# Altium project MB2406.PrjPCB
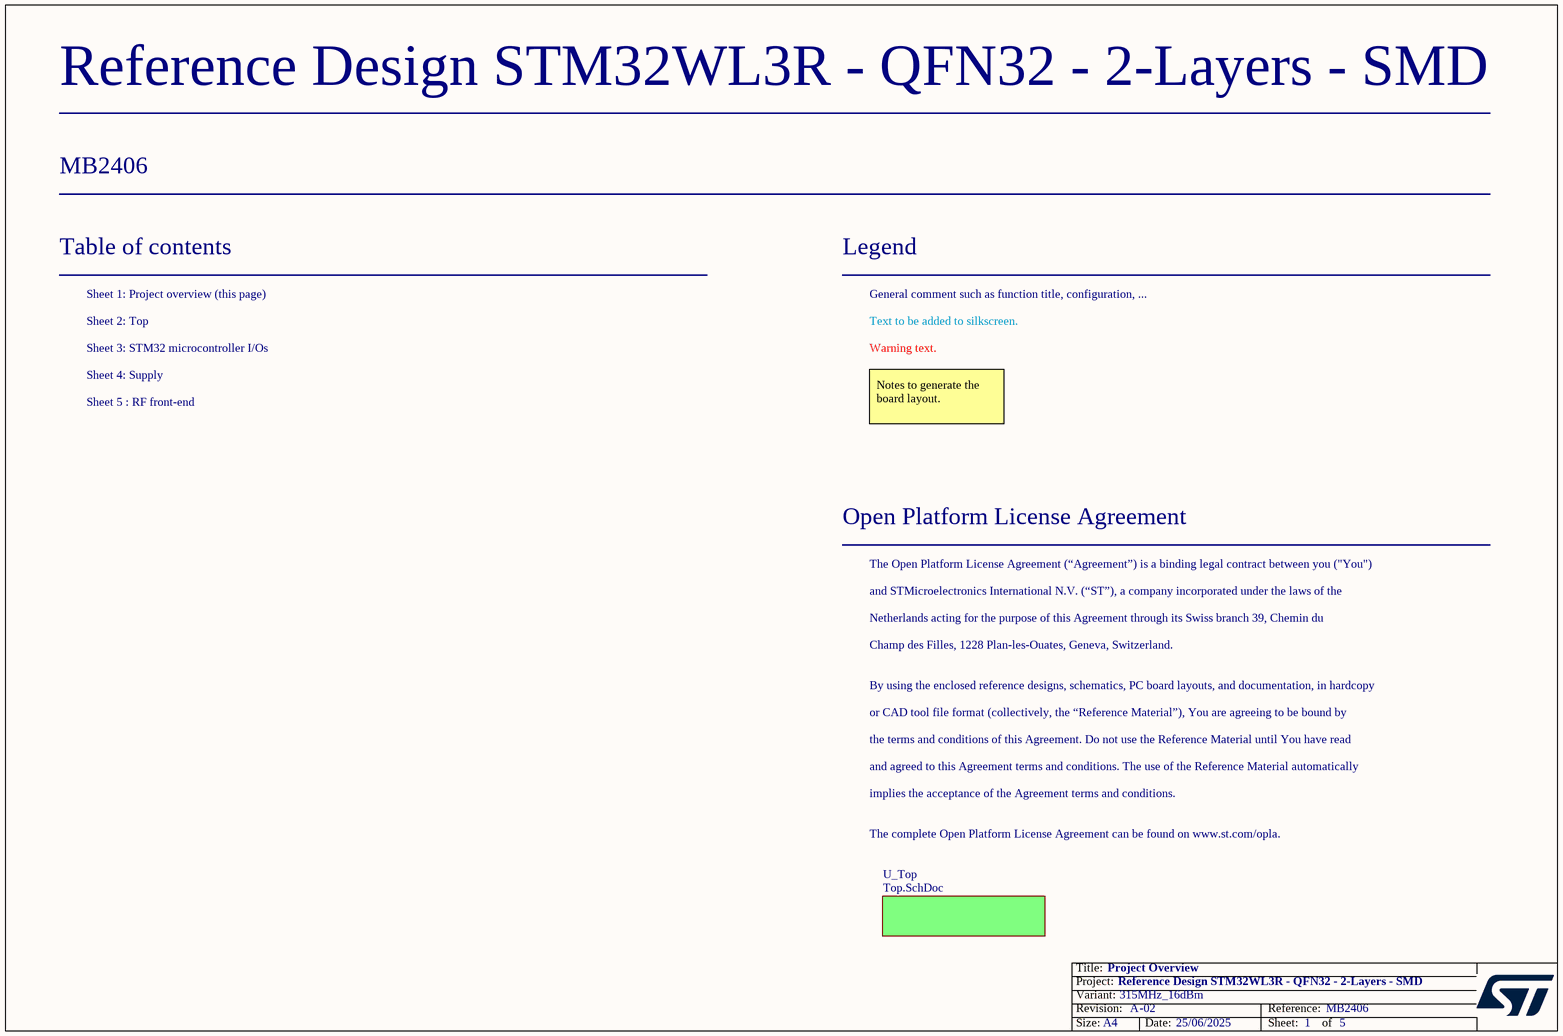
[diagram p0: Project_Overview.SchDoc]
Board_Assembly_Revision: 02; Board_Document_Date: 25/06/2025; Board_Name: Reference Design STM32WL3R - QFN32 - 2-Layers - SMD; Board_PCB_Revision: A; Board_Reference: MB2406; VariantName: 315MHz_16dBm
5 sheets, 71 parts. Net scope: flat (ports and power ports of the same name join across sheets).
Board file: MB2406.PcbDoc
Sheets:
  Project_Overview.SchDoc
    U_Top = Top.SchDoc
      Designator = MCU_IOs.SchDoc
      Designator = RF.SchDoc
      Designator = Supply.SchDoc

## Sheet Project_Overview.SchDoc: Project Overview
size A4; Date: Not used; ApprovedBy: Not used; CheckedBy: Not used; Author: Not used; CompanyName: STMicroelectronics; DrawnBy: Not used; Engineer: Not used; Organization: Not used; Address1: Not used; Address2: Not used; Address3: Not used; Address4: Not used; DocumentNumber: Not used; Revision: Not used; SheetNumber: 1; SheetTotal: 5

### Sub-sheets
U_Top = Top.SchDoc: no entries

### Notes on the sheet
- Table of contents
- Sheet 1: Project overview (this page)
- Legend
- General comment such as function title, configuration, ...
- Sheet 2: Top
- Sheet 3: STM32 microcontroller I/Os
- Sheet 4: Supply
- Text to be added to silkscreen.
- Warning text.
- Sheet 5 : RF front-end
- Notes to generate the board layout.
- Open Platform License Agreement
- The Open Platform License Agreement (“Agreement”) is a binding legal contract between you ("You")
- and STMicroelectronics International N.V. (“ST”), a company incorporated under the laws of the
- Netherlands acting for the purpose of this Agreement through its Swiss branch 39, Chemin du
- Champ des Filles, 1228 Plan-les-Ouates, Geneva, Switzerland.
- By using the enclosed reference designs, schematics, PC board layouts, and documentation, in hardcopy
- or CAD tool file format (collectively, the “Reference Material”), You are agreeing to be bound by
- the terms and conditions of this Agreement. Do not use the Reference Material until You have read
- and agreed to this Agreement terms and conditions. The use of the Reference Material automatically
- implies the acceptance of the Agreement terms and conditions.
- The complete Open Platform License Agreement can be found on www.st.com/opla.

## Sheet Top.SchDoc: Top Schematic
size A4; Date: Not used; ApprovedBy: Not used; CheckedBy: Not used; Author: Not used; CompanyName: STMicroelectronics; DrawnBy: Not used; Engineer: Not used; Organization: Not used; Address1: Not used; Address2: Not used; Address3: Not used; Address4: Not used; DocumentNumber: Not used; Revision: Not used; SheetNumber: 2; SheetTotal: 4
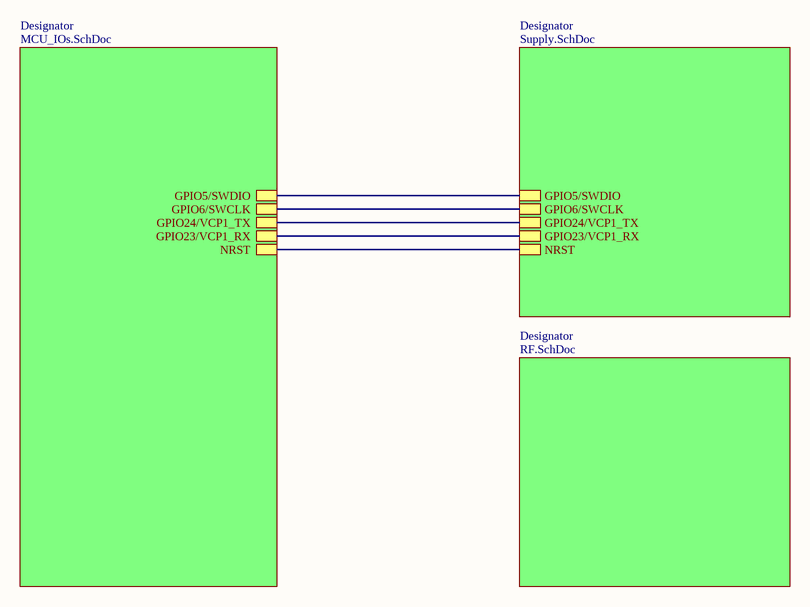
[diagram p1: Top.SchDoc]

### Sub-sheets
Designator = MCU_IOs.SchDoc: NRST, GPIO5/SWDIO, GPIO6/SWCLK, GPIO24/VCP1_TX, GPIO23/VCP1_RX
Designator = RF.SchDoc: no entries
Designator = Supply.SchDoc: NRST, GPIO5/SWDIO, GPIO6/SWCLK, GPIO23/VCP1_RX, GPIO24/VCP1_TX

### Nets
(unnamed): sheet Designator/NRST, sheet Designator/NRST
(unnamed): sheet Designator/GPIO5/SWDIO, sheet Designator/GPIO5/SWDIO  [a separate net that carries the same name]
(unnamed): sheet Designator/GPIO6/SWCLK, sheet Designator/GPIO6/SWCLK  [a separate net that carries the same name]
(unnamed): sheet Designator/GPIO24/VCP1_TX, sheet Designator/GPIO24/VCP1_TX  [a separate net that carries the same name]
(unnamed): sheet Designator/GPIO23/VCP1_RX, sheet Designator/GPIO23/VCP1_RX  [a separate net that carries the same name]

## Sheet MCU_IOs.SchDoc: STM32 I/Os & Clock
size A4; Date: Not used; ApprovedBy: Not used; CheckedBy: Not used; Author: Not used; CompanyName: STMicroelectronics; DrawnBy: Not used; Engineer: Not used; Organization: Not used; Address1: Not used; Address2: Not used; Address3: Not used; Address4: Not used; DocumentNumber: Not used; Revision: Not used; SheetNumber: 3; SheetTotal: 5
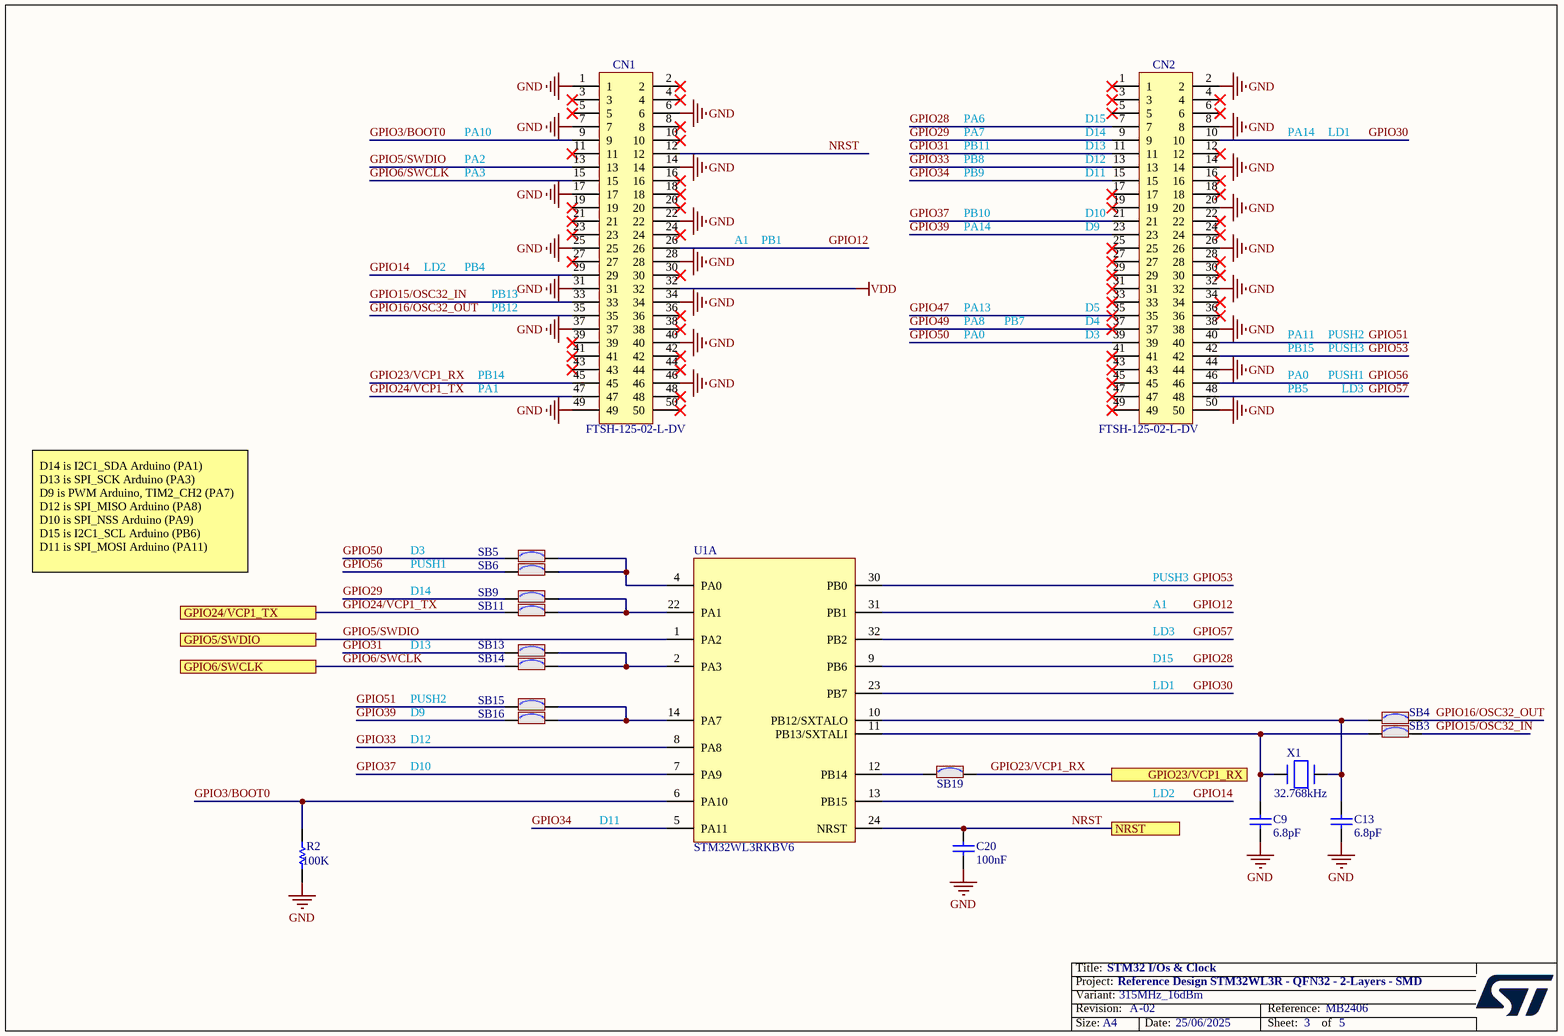
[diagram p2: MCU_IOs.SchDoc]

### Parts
C9  value 6.8pF  [C0402_MURATA_GJM-GRM15_H0P5]  (hidden comment: Capacitor)
C13  value 6.8pF  [C0402_MURATA_GJM-GRM15_H0P5]  (hidden comment: Capacitor)
C20  value 100nF  [C0402_MURATA_GJM-GRM15_H0P5]  (hidden comment: Capacitor)
CN1  FTSH-125-02-L-DV  [CON_SAMTEC_FTSH-125-02-L-DV]
CN2  FTSH-125-02-L-DV  [CON_SAMTEC_FTSH-125-02-L-DV]
R2  value 100K  [R0402]  (hidden comment: Resistor)
SB3  SB_ON  [SOLDER-BRIDGE_R0402-0R]  (value not drawn)
SB4  SB_ON  [SOLDER-BRIDGE_R0402-0R]  (value not drawn)
SB5  SB_ON  [SOLDER-BRIDGE_R0402-0R]  (value not drawn)
SB6  SB_ON  [SOLDER-BRIDGE_R0402-0R]  (value not drawn)
SB9  SB_ON  [SOLDER-BRIDGE_R0402-0R]  (value not drawn)
SB11  SB_ON  [SOLDER-BRIDGE_R0402-0R]  (value not drawn)
SB13  SB_ON  [SOLDER-BRIDGE_R0402-0R]  (value not drawn)
SB14  SB_ON  [SOLDER-BRIDGE_R0402-0R]  (value not drawn)
SB15  SB_ON  [SOLDER-BRIDGE_R0402-0R]  (value not drawn)
SB16  SB_ON  [SOLDER-BRIDGE_R0402-0R]  (value not drawn)
SB19  SB_ON  [SOLDER-BRIDGE_R0402-0R]  (value not drawn)
U1  value STM32WL3RKBV6  [ICC_VFQFPN32-EPAD_5X5_P050]  (hidden comment: IC_STM32WL3R)  (part A of 3)
X1  value 32.768kHz  [CRY_NX2012SA_2P]  (hidden comment: XTAL_2_PINS)

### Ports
GPIO5/SWDIO, GPIO6/SWCLK, GPIO23/VCP1_RX, GPIO24/VCP1_TX, NRST

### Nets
GND: C9.1 C13.1 C20.1 CN1.1 CN1.6 CN1.7 CN1.14 CN1.17 CN1.22 CN1.25 CN1.28 CN1.31 CN1.34 CN1.37 CN1.40 CN1.46 CN1.49 CN2.2 CN2.8 CN2.14 CN2.20 CN2.26 CN2.32 CN2.38 CN2.44 CN2.50 R2.1
VDD: CN1.32
GPIO3/BOOT0: CN1.9 R2.2 U1.6(PA10)
GPIO5/SWDIO: CN1.13 U1.1(PA2) ; port GPIO5/SWDIO
GPIO6/SWCLK: CN1.15 SB14.1 ; port GPIO6/SWCLK
GPIO12: CN1.26 U1.31(PB1)
GPIO14: CN1.29 U1.13(PB15)
GPIO15/OSC32_IN: CN1.33 SB3.2
GPIO16/OSC32_OUT: CN1.35 SB4.2
GPIO23/VCP1_RX: CN1.45 SB19.2 ; port GPIO23/VCP1_RX
GPIO24/VCP1_TX: CN1.47 SB11.1 ; port GPIO24/VCP1_TX
GPIO28: CN2.7 U1.9(PB6)
GPIO29: CN2.9 SB9.1
GPIO30: CN2.10 U1.23(PB7)
GPIO31: CN2.11 SB13.1
GPIO33: CN2.13 U1.8(PA8)
GPIO34: CN2.15 U1.5(PA11)
GPIO37: CN2.21 U1.7(PA9)
GPIO39: CN2.23 SB16.1
GPIO47: CN2.35
GPIO49: CN2.37
GPIO50: CN2.39 SB5.1
GPIO51: CN2.40 SB15.1
GPIO53: CN2.42 U1.30(PB0)
GPIO56: CN2.46 SB6.1
GPIO57: CN2.48 U1.32(PB2)
NRST: C20.2 CN1.12 U1.24(NRST) ; port NRST
NetC9_2: C9.2 SB3.1 U1.11(PB13/SXTALI) X1.2(X2)
NetC13_2: C13.2 SB4.1 U1.10(PB12/SXTALO) X1.1(X1)
NetSB5_2: SB5.2 SB6.2 U1.4(PA0)
NetSB9_2: SB9.2 SB11.2 U1.22(PA1)
NetSB13_2: SB13.2 SB14.2 U1.2(PA3)
NetSB15_2: SB15.2 SB16.2 U1.14(PA7)
NetSB19_1: SB19.1 U1.12(PB14)

Not connected (* = marked no-connect by the designer): CN1 2* 3* 4* 5* 8* 10* 11* 16* 18* 19* 20* 21* 23* 24* 27* 30* 36* 38* 39* 41* 42* 43* 44* 48* 50*; CN2 1* 3* 4* 5* 6* 12* 16* 17* 18* 19* 22* 24* 25* 27* 28* 29* 30* 31* 33* 34* 36* 41* 43* 45* 47* 49*

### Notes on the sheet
- PA10
- PA2
- PA3
- PA7
- PA6
- PB8
- PB11
- PB9
- (near CN2) D11
- (near CN2) D13
- (near CN2) D14
- (near CN2) D15
- (near CN2) D12
- PA14
- LD1
- A1
- PB1
- PB10
- (near CN2) D10
- (near CN2) D9
- LD2
- PB4
- PB13
- PB12
- PA13
- (near CN2) D5
- PB14
- PA0
- PA8
- PB7
- (near CN2) D4
- (near CN2) D3
- PA11
- PB15
- PUSH1
- PUSH2
- PUSH3
- PA1
- PB5
- LD3
- D14 is I2C1_SDA Arduino (PA1)
  D13 is SPI_SCK Arduino (PA3)
  D9 is PWM Arduino, TIM2_CH2 (PA7)
  D12 is SPI_MISO Arduino (PA8)
  D10 is SPI_NSS Arduino (PA9)
  D15 is I2C1_SCL Arduino (PB6)
  D11 is SPI_MOSI Arduino (PA11)
- D3
- D14
- D13
- D9
- D15
- D10
- D12
- D11

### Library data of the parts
C9 C13 = MCD-03452: Capacitor, MLCC, 6.8pF, 50V,C0G/NP0, +/-0.05pF, 0402, T=0.5mm; Part_Preference: Recommended; Manufacturer: MURATA; Manufacturer_Part_Number: GJM1555C1H6R8WB01; Component_Country_Of_Origin: Japan, Singapore; ShowFields: YES; ID: 5568
C20 = MCD-00006: Capacitor, MLCC, 100nF, 16V, X7R, +/-10%, 0402, T=0.5mm; Part_Preference: Recommended; Manufacturer: YAGEO; Manufacturer_Part_Number: CC0402KRX7R7BB104; Partial_Alternate_Internal_Part_Number: MCD-03299; Order_Code_RS: 9402047; Component_Country_Of_Origin: China; ShowFields: YES; ID: 2474
CN1 CN2 = MCD-02746: Header, 25x2, 12.7mm, VR, SMD, T=4.83mm; Part_Type: Connector; Part_Preference: Recommended; Manufacturer: SAMTEC; Value: Header 25x2; ShowFields: YES; ID: 4858; Component_Country_Of_Origin: China, Costa Rica, Malaysia, USA, Vietnam
R2 = MCD-00059: Resistor, 100K, 0402, +/-1%, 1/16W; Part_Preference: Recommended; Manufacturer: YAGEO; Manufacturer_Part_Number: RC0402FR-07100KL; Partial_Alternate_Internal_Part_Number: MCD-03301; Order_Code_RS: 2421891; Component_Country_Of_Origin: China; ShowFields: YES; ID: 2533
SB3-SB6 SB9 SB11 SB13-SB16 SB19 = MCD-01618: Solder Bridge 0402 ON; Part_Type: Misc; Part_Preference: Recommended; Manufacturer: YAGEO; Manufacturer_Part_Number: RC0402JR-070RL; Order_Code_RS: 618-5804; Component_Country_Of_Origin: China
U1 = MCD-04431: MCU, ARM Cortex-M0 32-bit, 128KB Flash, 16KB SRAM, With Crypto; Part_Type: IC; Part_Preference: Recommended; Manufacturer: STMICROELECTRONICS; ShowFields: YES; ID: 6547
X1 = MCD-01445: Crystal, 32.768kHz, 7pF, +/-20ppm, 80K, 2.05x1.2mm; BMS_Part_Number: 9157043; Part_Type: Crystal_Osc; Part_Preference: Recommended; Manufacturer: NDK; Manufacturer_Part_Number: NX2012SA-32.768KHZ-EXS00A-MU00389; Component_Country_Of_Origin: Unknown; ShowFields: YES; ID: 3545

## Sheet RF.SchDoc: STM32 RF
size A4; Date: Not used; ApprovedBy: Not used; CheckedBy: Not used; Author: Not used; CompanyName: STMicroelectronics; DrawnBy: Not used; Engineer: Not used; Organization: Not used; Address1: Not used; Address2: Not used; Address3: Not used; Address4: Not used; DocumentNumber: Not used; Revision: Not used; SheetNumber: 5; SheetTotal: 5
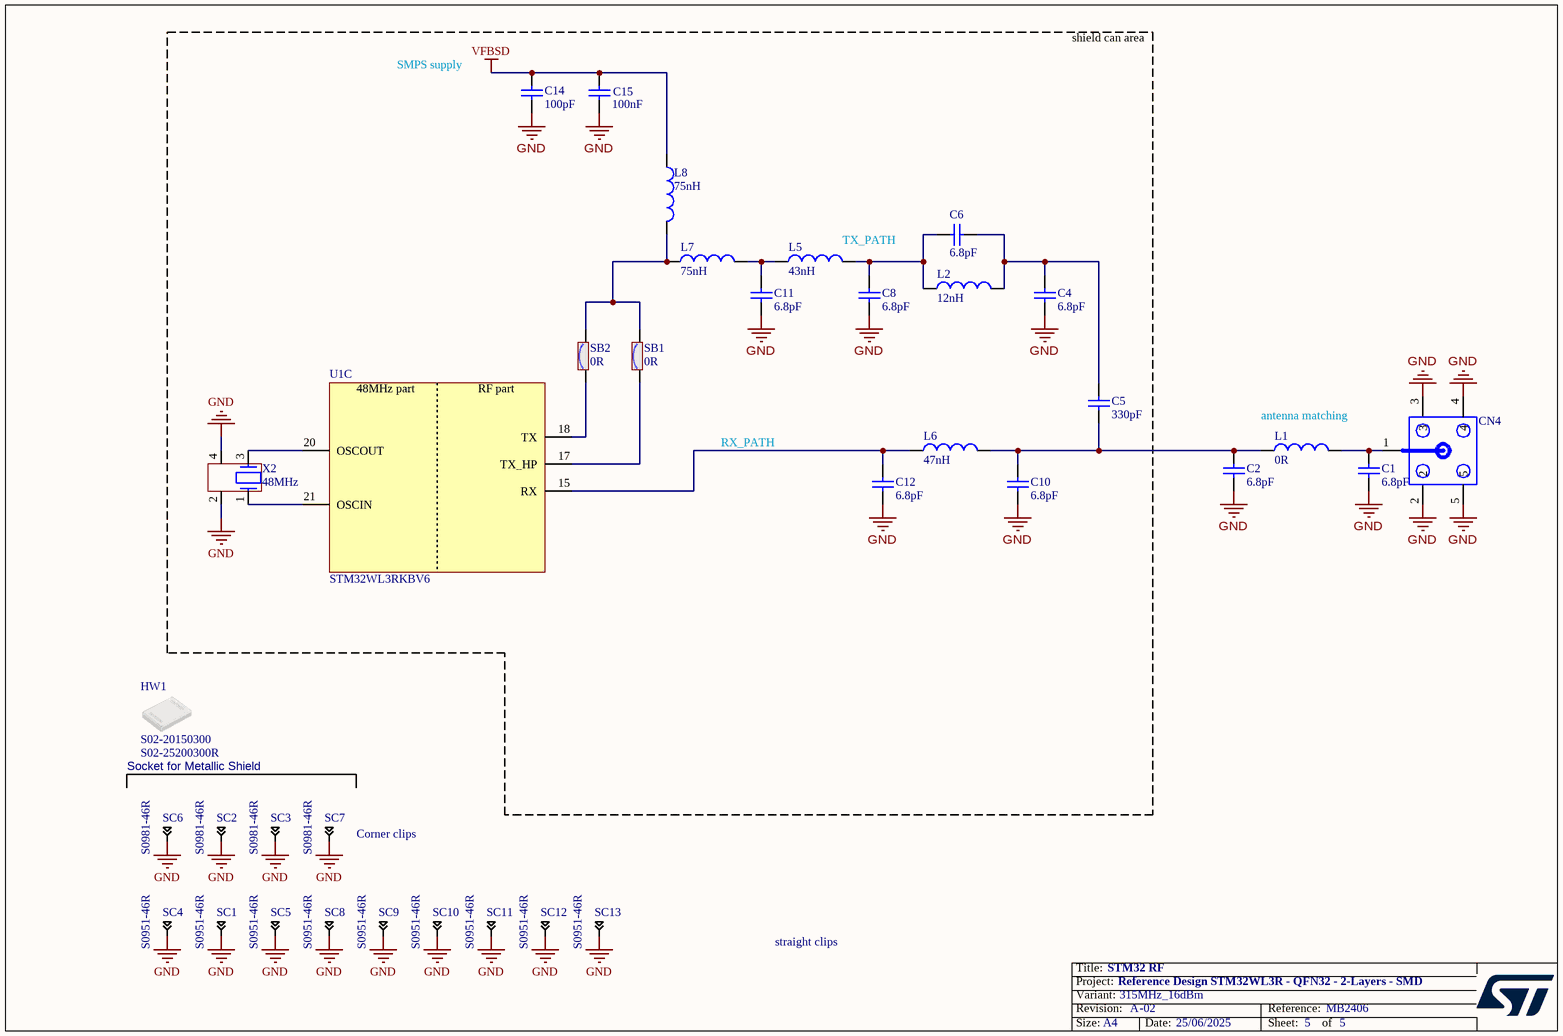
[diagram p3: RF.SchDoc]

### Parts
C1  value 6.8pF  [C0402_MURATA_GJM-GRM15_H0P5]  (hidden comment: Capacitor)
C2  value 6.8pF  [C0402_MURATA_GJM-GRM15_H0P5]  (hidden comment: Capacitor)
C4  value 6.8pF  [C0402_MURATA_GJM-GRM15_H0P5]  (hidden comment: Capacitor)
C5  value 330pF  [C0402_MURATA_GJM-GRM15_H0P5]  (hidden comment: Capacitor)
C6  value 6.8pF  [C0402_MURATA_GJM-GRM15_H0P5]  (hidden comment: Capacitor)
C8  value 6.8pF  [C0402_MURATA_GJM-GRM15_H0P5]  (hidden comment: Capacitor)
C10  value 6.8pF  [C0402_MURATA_GJM-GRM15_H0P5]  (hidden comment: Capacitor)
C11  value 6.8pF  [C0402_MURATA_GJM-GRM15_H0P5]  (hidden comment: Capacitor)
C12  value 6.8pF  [C0402_MURATA_GJM-GRM15_H0P5]  (hidden comment: Capacitor)
C14  value 100pF  [C0402_MURATA_GJM-GRM15_H0P5]  (hidden comment: Capacitor)
C15  value 100nF  [C0402_MURATA_GJM-GRM15_H0P5]  (hidden comment: Capacitor)
CN4  SMA-J-P-H-ST-EM1  [142-0701-851]  (value not drawn)
HW1  S02-20150300  value S02-25200300R  [SHIELD_HARWIN_S02-25200300_20X25_H3]
L1  value 0R  [IND_0402_MURATA_LQG15HSXXXX02_H0P5]  (hidden comment: Inductor)
L2  value 12nH  [IND_0402_MURATA_LQW15ANXXXX00_H0P5]  (hidden comment: Inductor)
L5  value 43nH  [IND_0402_MURATA_LQW15ANXXXX00_H0P5]  (hidden comment: Inductor)
L6  value 47nH  [IND_0402_MURATA_LQW15ANXXXX00_H0P5]  (hidden comment: Inductor)
L7  value 75nH  [IND_0402_MURATA_LQW15ANXXXX00_H0P5]  (hidden comment: Inductor)
L8  value 75nH  [IND_0402_MURATA_LQW15ANXXXX00_H0P5]  (hidden comment: Inductor)
SB1  value 0R  [SOLDER-BRIDGE_R0201_0R]  (hidden comment: SB_ON)
SB2  value 0R  [SOLDER-BRIDGE_R0201_0R]  (hidden comment: SB_ON)
SC1  value S0951-46R  [CLIP_HARWIN_S0951-46R]  (hidden comment: Shield-clip_S0951-46R)
SC2  value S0981-46R  [CLIP_HARWIN_S0981-46R]  (hidden comment: Shield-clip_S0951-46R)
SC3  value S0981-46R  [CLIP_HARWIN_S0981-46R]  (hidden comment: Shield-clip_S0951-46R)
SC4  value S0951-46R  [CLIP_HARWIN_S0951-46R]  (hidden comment: Shield-clip_S0951-46R)
SC5  value S0951-46R  [CLIP_HARWIN_S0951-46R]  (hidden comment: Shield-clip_S0951-46R)
SC6  value S0981-46R  [CLIP_HARWIN_S0981-46R]  (hidden comment: Shield-clip_S0951-46R)
SC7  value S0981-46R  [CLIP_HARWIN_S0981-46R]  (hidden comment: Shield-clip_S0951-46R)
SC8  value S0951-46R  [CLIP_HARWIN_S0951-46R]  (hidden comment: Shield-clip_S0951-46R)
SC9  value S0951-46R  [CLIP_HARWIN_S0951-46R]  (hidden comment: Shield-clip_S0951-46R)
SC10  value S0951-46R  [CLIP_HARWIN_S0951-46R]  (hidden comment: Shield-clip_S0951-46R)
SC11  value S0951-46R  [CLIP_HARWIN_S0951-46R]  (hidden comment: Shield-clip_S0951-46R)
SC12  value S0951-46R  [CLIP_HARWIN_S0951-46R]  (hidden comment: Shield-clip_S0951-46R)
SC13  value S0951-46R  [CLIP_HARWIN_S0951-46R]  (hidden comment: Shield-clip_S0951-46R)
U1  value STM32WL3RKBV6  [ICC_VFQFPN32-EPAD_5X5_P050]  (hidden comment: IC_STM32WL3R)  (part C of 3)
X2  value 48MHz  [CRY_NX1612SA_4P]  (hidden comment: XTAL_4_PINS)

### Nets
GND: C1.1 C2.1 C4.1 C8.1 C10.1 C11.1 C12.1 C14.2 C15.1 CN4.2 CN4.3 CN4.4 CN4.5 SC1.1 SC2.1 SC3.1 SC4.1 SC5.1 SC6.1 SC7.1 SC8.1 SC9.1 SC10.1 SC11.1 SC12.1 SC13.1 X2.2 X2.4
VFBSD: C14.1 C15.2 L8.1
NetC1_2: C1.2 CN4.1 L1.2
NetC2_2: C2.2 C5.2 C10.2 L1.1 L6.2
NetC4_2: C4.2 C5.1 C6.2 L2.2
NetC6_1: C6.1 C8.2 L2.1 L5.2
NetC11_2: C11.2 L5.1 L7.2
NetC12_2: C12.2 L6.1 U1.15(RX)
NetL7_1: L7.1 L8.2 SB1.2 SB2.2
NetSB1_1: SB1.1 U1.17(TX_HP)
NetSB2_1: SB2.1 U1.18(TX)
NetU1_20: U1.20(OSCOUT) X2.3
NetU1_21: U1.21(OSCIN) X2.1

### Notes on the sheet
- shield can area
- SMPS supply
- (near L5) TX_PATH
- RX_PATH
- antenna matching
- Socket for Metallic Shield
- (near SC7) Corner clips
- straight clips

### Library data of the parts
C1 C2 C4 C6 C8 C10-C12 = MCD-03452: as C9 on sheet MCU_IOs
C5 = MCD-04785: Capacitor, MLCC, 330pF, 50V, C0G, 5%, 0402, T=0.5mm; Part_Preference: Recommended; Manufacturer: MURATA; Manufacturer_Part_Number: GCM1555C1H331JA16; Component_Country_Of_Origin: Japan, China, Philippines, Singapore; ShowFields: YES; ID: 6901
C14 = MCD-03446: Capacitor, MLCC, 100pF, 50V, C0G/NP0, +/-1%, 0402, T=0.5mm; Part_Preference: Recommended; Manufacturer: MURATA; Manufacturer_Part_Number: GCM1555C1H101FA16; Order_Code_RS: 247-7780; Component_Country_Of_Origin: China, Japan, Philippines, Singapore; ShowFields: YES; ID: 5562
C15 = MCD-03442: Capacitor, MLCC, 100nF, ±10%, X7R, 25V, 0402, T=0.5mm; Part_Preference: Recommended; Manufacturer: MURATA; Manufacturer_Part_Number: GRM155R71E104KE14D; Order_Code_RS: 247-8011; ShowFields: YES; ID: 5558
CN4 = MCD-02072: Jack_SMA, VR, PCB edge, 50R, T=7.92mm; Part_Type: Connector; Part_Preference: Recommended; Manufacturer: CINCH; Value: Jack_SMA_142-0701-851; Order_Code_RS: 885-7532; Component_Country_Of_Origin: USA°°; ShowFields: YES; ID: 4172
HW1 = MCD-03503: RFI shield CAN, 25x20x3mm; Part_Type: Misc; Part_Preference: Recommended; Manufacturer: HARWIN; Order_Code_RS: 247-9197; Component_Country_Of_Origin: UK; ShowFields: YES; ID: 5619
L1 = MCD-01937: Resistor, 0R, 0402, +/-5%, 1/16W; Part_Preference: Recommended; Manufacturer: YAGEO; Manufacturer_Part_Number: RC0402JR-070RL; Order_Code_RS: 618-5804; Component_Country_Of_Origin: China; ShowFields: YES; ID: 4037
L2 = MCD-03456: Inductor, 12nH, +/-2%, 500mA, 0R14, 0402, T=0.5mm; Part_Preference: Recommended; Manufacturer: MURATA; Manufacturer_Part_Number: LQW15AN12NG00D; Order_Code_RS: 124-8172; Component_Country_Of_Origin: Japan, Malaysia; ShowFields: YES; ID: 5572
L5 = MCD-04787: Inductor, 43nH, +/-2%, Itemp= 515mA, 0R516, 0402, T=0.5mm, Qmin=30; Part_Preference: Recommended; Manufacturer: MURATA; Manufacturer_Part_Number: LQW15AN43NG80; Order_Code_RS: N\A; Component_Country_Of_Origin: Japan, Malaysia; ShowFields: YES; ID: 6903
L6 = MCD-02075: Inductor, 47nH, +/-2%, Itemp=210mA max, 0R108, 0402, T=0.6mm, Qmin=30; Part_Preference: Recommended; Manufacturer: MURATA; Manufacturer_Part_Number: LQW15AN47NG00; Order_Code_RS: 792-6445; Component_Country_Of_Origin: Japan°°; ShowFields: YES; ID: 4175
L7 L8 = MCD-04786: Inductor, 75nH, +/-2%, Itemp=320mA, 1R224, 0402, T=0.5mm, Qmin=25; Part_Preference: Recommended; Manufacturer: MURATA; Manufacturer_Part_Number: LQW15AN75NG80; Order_Code_RS: N\A; Component_Country_Of_Origin: Japan, Malaysia; ShowFields: YES; ID: 6902
SB1 SB2 = MCD-03219: Solder Bridge ON, 0R, 0201, 1/20W; Part_Type: Misc; Part_Preference: Recommended; Manufacturer: YAGEO; Manufacturer_Part_Number: RC0201JR-070RL; Order_Code_RS: 198-7623; Component_Country_Of_Origin: China; ShowFields: YES; ID: 5335
SC1 SC4 SC5 SC8 = MCD-01587: shield clip Harwin S0951-46R to fix RF shielded cavity; Part_Type: Misc; Part_Preference: Recommended; Component_Country_Of_Origin: South Korea
SC2 SC3 SC6 SC7 = MCD-02164: shield clip Harwin S0981-46R to fix RF shielded cavity - SMT RFI Shield Clip, Corner (T+R); Part_Type: Misc; Part_Preference: Recommended; Order_Code_RS: 161-3702; Component_Country_Of_Origin: South Korea; ShowFields: YES; ID: 4264
SC9-SC13 = MCD-01587: RFI shield clip mini TIN SMD; Part_Type: Mechanical; Part_Preference: Recommended; Manufacturer: HARWIN; Component_Country_Of_Origin: South Korea; ShowFields: YES; ID: 3687
U1 = MCD-04431: as U1 on sheet MCU_IOs
X2 = MCD-03559: Crystal, 48MHz, 8pF, +/-10 ppm, 22R, 1.6x1.2mm; Part_Type: Crystal_Osc; Part_Preference: Recommended; Manufacturer: NDK; Manufacturer_Part_Number: NX1612SA-48.000 MHz-EXS00A-CS12140; ShowFields: YES; ID: 5675

## Sheet Supply.SchDoc: STM32 power
size A4; Date: Not used; ApprovedBy: Not used; CheckedBy: Not used; Author: Not used; CompanyName: STMicroelectronics; DrawnBy: Not used; Engineer: Not used; Organization: Not used; Address1: Not used; Address2: Not used; Address3: Not used; Address4: Not used; DocumentNumber: Not used; Revision: Not used; SheetNumber: 4; SheetTotal: 5
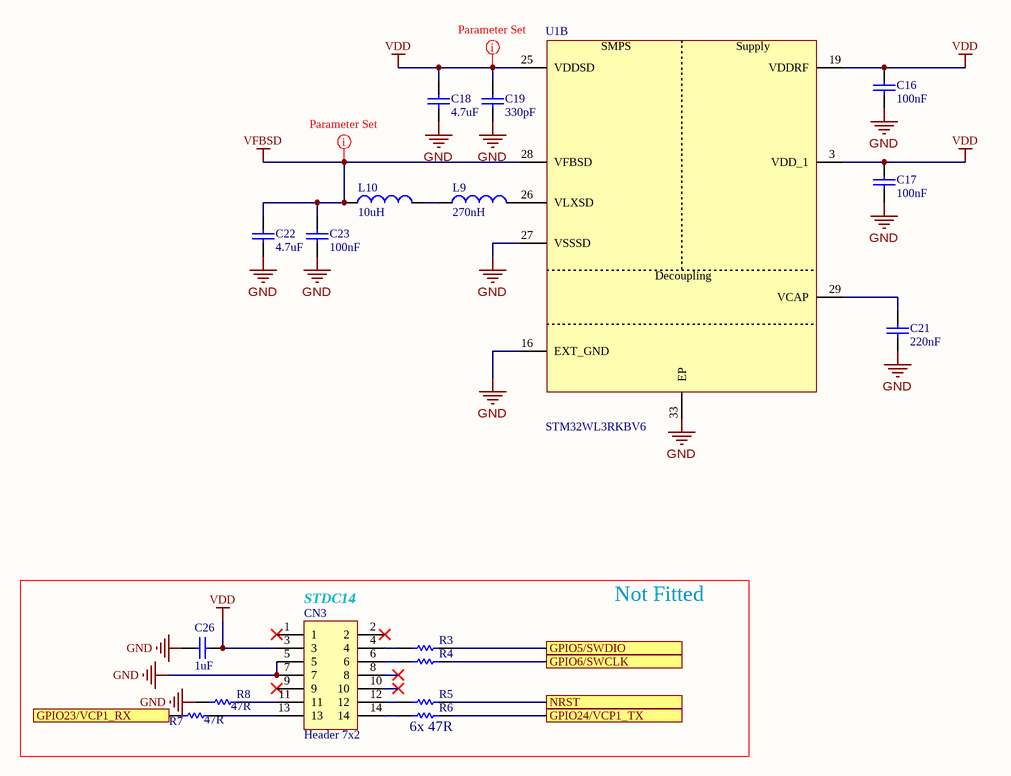
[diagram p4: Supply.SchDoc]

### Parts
C16  value 100nF  [C0402_MURATA_GJM-GRM15_H0P5]  (hidden comment: Capacitor)
C17  value 100nF  [C0402_MURATA_GJM-GRM15_H0P5]  (hidden comment: Capacitor)
C18  value 4.7uF  [C0402_MURATA_GJM-GRM15_H0P5]  (hidden comment: Capacitor)
C19  value 330pF  [C0402_MURATA_GJM-GRM15_H0P5]  (hidden comment: Capacitor)
C21  value 220nF  [C0402_MURATA_GJM-GRM15_H0P5]  (hidden comment: Capacitor)
C22  value 4.7uF  [C0402_MURATA_GJM-GRM15_H0P5]  (hidden comment: Capacitor)
C23  value 100nF  [C0402_MURATA_GJM-GRM15_H0P5]  (hidden comment: Capacitor)
C26  value 1uF  [C0603]  (hidden comment: Capacitor)
CN3  Header 7x2  [CON_SAMTEC_FTSH-107-01-L-DV-K-A]
L9  value 270nH  [IND_0402_MURATA_LQG15HSXXXX02_H0P5]  (hidden comment: Inductor)
L10  value 10uH  [IND_0805_MURATA_LQM21]  (hidden comment: Inductor)
R3  Resistor  [R0402]  (value not drawn)
R4  Resistor  [R0402]  (value not drawn)
R5  Resistor  [R0402]  (value not drawn)
R6  Resistor  [R0402]  (value not drawn)
R7  value 47R  [R0402]  (hidden comment: Resistor)
R8  value 47R  [R0402]  (hidden comment: Resistor)
U1  value STM32WL3RKBV6  [ICC_VFQFPN32-EPAD_5X5_P050]  (hidden comment: IC_STM32WL3R)  (part B of 3)

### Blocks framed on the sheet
Not Fitted: C26 CN3 R3-R8

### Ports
GPIO5/SWDIO, GPIO6/SWCLK, GPIO23/VCP1_RX, GPIO24/VCP1_TX, NRST

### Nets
GND: C16.1 C17.1 C18.1 C19.2 C21.1 C22.1 C23.1 C26.1 CN3.5 CN3.7 R8.1 U1.16(EXT_GND) U1.27(VSSSD) U1.33(EP)
VDD: C16.2 C17.2 C18.2 C19.1 C26.2 CN3.3 U1.3(VDD_1) U1.19(VDDRF) U1.25(VDDSD)
VFBSD: C22.2 C23.2 L10.1 U1.28(VFBSD)
GPIO5/SWDIO: R3.2 ; port GPIO5/SWDIO
GPIO6/SWCLK: R4.2 ; port GPIO6/SWCLK
GPIO23/VCP1_RX: R7.1 ; port GPIO23/VCP1_RX
GPIO24/VCP1_TX: R6.2 ; port GPIO24/VCP1_TX
NRST: R5.2 ; port NRST
NetC21_2: C21.2 U1.29(VCAP)
NetCN3_4: CN3.4 R3.1
NetCN3_6: CN3.6 R4.1
NetCN3_11: CN3.11 R8.2
NetCN3_12: CN3.12 R5.1
NetCN3_13: CN3.13 R7.2
NetCN3_14: CN3.14 R6.1
NetL9_1: L9.1 L10.2
NetL9_2: L9.2 U1.26(VLXSD)

Not connected (* = marked no-connect by the designer): CN3 1* 2* 8* 9* 10*

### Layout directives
net class VDD: VDD
net class VFBSD: VFBSD

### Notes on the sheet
- (near CN3) STDC14
- (near R6) 6x 47R

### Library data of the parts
C16 C17 C23 = MCD-03442: Capacitor, MLCC, 100nF, 25V, X7R, +/-10%, 0402, T=0.5mm; Part_Preference: Recommended; Manufacturer: MURATA; Manufacturer_Part_Number: GRM155R71E104KE14; Order_Code_RS: 247-8011; Component_Country_Of_Origin: China, Japan, Philippines, Singapore; ShowFields: YES; ID: 5558
C18 C22 = MCD-03431: Capacitor, MLCC, 4.7uF, 10V, X5R, +/-20%, 0402, T=0.5mm; Part_Preference: Recommended; Manufacturer: MURATA; Manufacturer_Part_Number: GRM155R61A475MEAA; Order_Code_RS: 172-6870; Component_Country_Of_Origin: China, Japan, Philippines, Singapore; ShowFields: YES; ID: 5547
C19 = MCD-04785: as C5 on sheet RF
C21 = MCD-03077: Capacitor, MLCC, 220nF, 35V, X6S, 10%, 0402, T=0.5mm; Part_Preference: Recommended; Manufacturer: MURATA; Manufacturer_Part_Number: GRM155C8YA224KE01; Component_Country_Of_Origin: Japan; ShowFields: YES; ID: 5193
C26 = MCD-00010: Capacitor, MLCC, 1uF, 16V, X5R, +/-10%, 0603, T=0.8mm; Part_Preference: Recommended; Manufacturer: YAGEO; Manufacturer_Part_Number: CC0603KRX5R7BB105; Order_Code_RS: 2370680; Component_Country_Of_Origin: China; ShowFields: YES; ID: 2470
CN3 = MCD-01531: Header, 7x2, 1.27mm, VR, T=5.97mm, FTSH series STDC14 without Alignment Pin; Part_Type: Connector; Part_Preference: Recommended; Manufacturer: SAMTEC; Manufacturer_Part_Number: FTSH-107-01-L-DV-K; Order_Code_RS: 179-9021; Component_Country_Of_Origin: China, Costa Rica, Malaysia, USA, Vietnam; ShowFields: YES; ID: 3631
L9 = MCD-03470: Inductor, 270nH, +/-2%, 110mA, 4R94, 0402, T=0.5mm; Part_Preference: Recommended; Manufacturer: MURATA; Manufacturer_Part_Number: LQG15HSR27G02; Component_Country_Of_Origin: Japan; ShowFields: YES; ID: 5586
L10 = MCD-02317: Inductor, 10uH, +/-20%, 100mA, 0R5, 0805, T=1.45mm; Part_Preference: Recommended; Manufacturer: MURATA; Manufacturer_Part_Number: LQM21FN100M80L; Order_Code_RS: 786-7074; Component_Country_Of_Origin: Japan°°; ShowFields: YES; ID: 4423
R3-R8 = MCD-00481: Resistor,47R,0402,1%,1/16W; Manufacturer_Part_Number: RC0402FR-0747RL; Manufacturer: YAGEO; Provided_By: Subcon
U1 = MCD-04431: as U1 on sheet MCU_IOs

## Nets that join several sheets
GND: MCU_IOs (27 pins), RF (28 pins), Supply (14 pins)
VDD: MCU_IOs (CN1.32), Supply (9 pins)
VFBSD: RF (C14.1 C15.2 L8.1), Supply (C22.2 C23.2 L10.1 U1.28)
GPIO5/SWDIO: MCU_IOs (CN1.13 U1.1), Supply (R3.2)
GPIO6/SWCLK: MCU_IOs (CN1.15 SB14.1), Supply (R4.2)
GPIO23/VCP1_RX: MCU_IOs (CN1.45 SB19.2), Supply (R7.1)
GPIO24/VCP1_TX: MCU_IOs (CN1.47 SB11.1), Supply (R6.2)
NRST: MCU_IOs (C20.2 CN1.12 U1.24), Supply (R5.2)

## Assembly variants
315MHz_16dBm: not fitted C1 C2 C4 C6 C8 C10 C12 C14 C23 C26 CN3 R3 R4 R5 R6 R7 R8 SB2 SB3 SB4 SB5 SB9 SB13 SB16; alternate parts L2 -> MCD-01937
